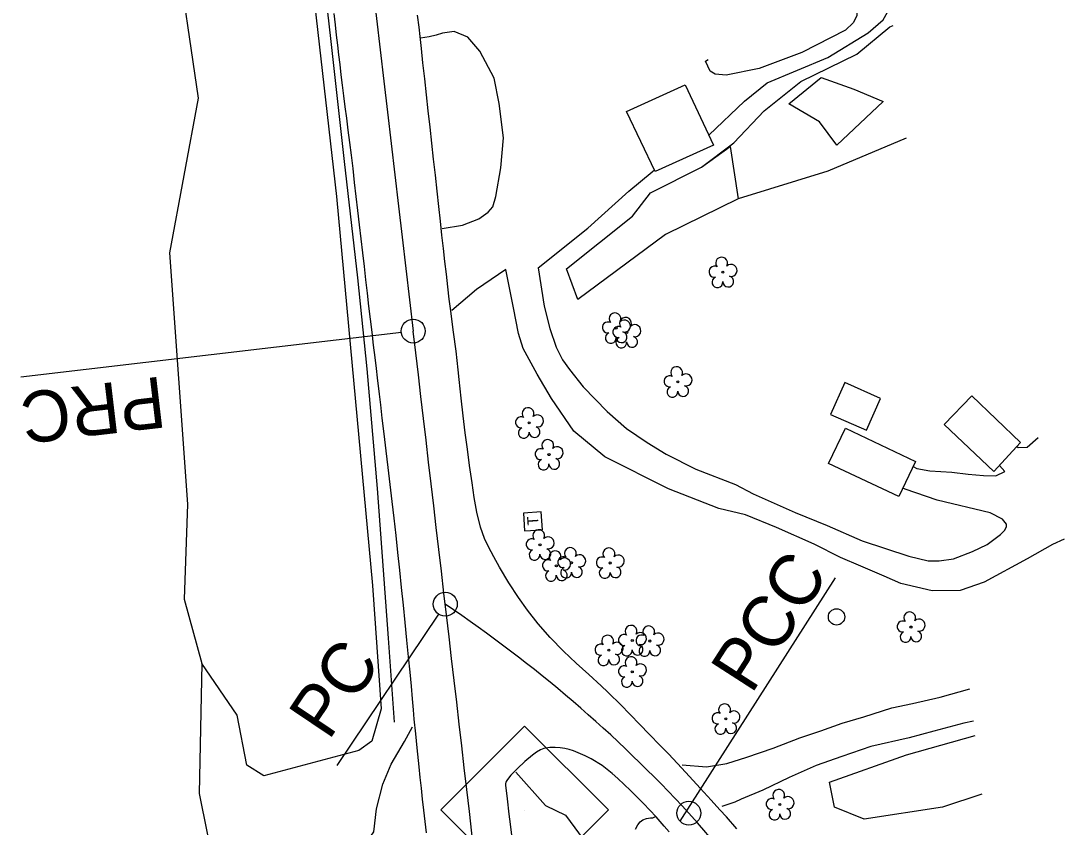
# Model space of a CAD drawing. Extents: x 476627 to 479509, y 495837 to 499842.
# Drawn here: x 477971.3 to 478298.1, y 497616.9 to 497869.6 of the extents above; entities that cross this region are included whole.
import ezdxf

# ---------------------------------------------------------------- set-up
doc = ezdxf.new("R2010")
doc.units = 0
for name, color, linetype in [('CTL Secondary Horizontal and Vertical CELL', 7, 'Continuous'), ('Exist Building Metal Canopy', 7, 'Continuous'), ('Exist Guardrail', 7, 'Continuous'), ('Exist Horizontal Alignment', 7, 'Continuous'), ('Exist Other Culture Well CELL', 7, 'Continuous'), ('Exist Roads EOP', 7, 'Continuous'), ('Exist Roads EOP Other', 7, 'Continuous'), ('Exist Roads Soil', 7, 'Continuous'), ('Exist Utilities Telephone Pedestal CELL', 7, 'Continuous'), ('Exist Vegetation Hedge Row', 7, 'Continuous'), ('Exist Vegetation Tree CELL', 7, 'Continuous'), ('Exist Vegetation Woods Line', 7, 'Continuous')]:
    doc.layers.add(name, color=color, linetype=linetype)

msp = doc.modelspace()

# ---------------------------------------------------------------- linework, layer by layer
at = {"layer": 'CTL Secondary Horizontal and Vertical CELL'}
msp.add_line((478128.95, 497622.27), (478128.95, 497622.27), dxfattribs=at)
msp.add_lwpolyline([(478102.87, 497622.36), (478129.08, 497648.57), (478155.33, 497622.32), (478129.13, 497596.11)], close=True, dxfattribs=at)
at = {"layer": 'Exist Building Metal Canopy'}
for points in [[(478179.35, 497849.53), (478188.26, 497830.61), (478169.99, 497822.42), (478160.98, 497841.23)], [(478224.89, 497746.19), (478236.2, 497741.3), (478240.55, 497751.23), (478229.44, 497756.28)]]:
    msp.add_lwpolyline(points, close=True, dxfattribs=at)
for points in [[(478269.23, 497752.05), (478284.47, 497737.42), (478276.12, 497728.32), (478260.55, 497743.12), (478269.23, 497752.05)], [(478229.68, 497741.92), (478251.56, 497731.45), (478246.35, 497720.51), (478224.32, 497730.87), (478229.68, 497741.92)]]:
    msp.add_lwpolyline(points, dxfattribs=at)
at = {"layer": 'Exist Guardrail'}
msp.add_line((478088.31, 497649.84), (478086.46, 497676.11), dxfattribs=at)
msp.add_lwpolyline([(478086.46, 497676.11), (478082.96, 497723.06), (478079.76, 497760.55), (478076.82, 497789.03), (478072.71, 497825.54), (478068.52, 497863.08), (478065.12, 497892.72), (478060.78, 497929.66), (478056.27, 497968.59), (478052.93, 497997.1), (478051.65, 498003.96), (478049.7, 498012.85), (478047.39, 498020.65), (478045.09, 498026.62), (478042.93, 498030.39), (478040.52, 498033.29), (478038.53, 498035.24)], dxfattribs=at)
at = {"layer": 'Exist Horizontal Alignment'}
for p, q in [((478090.48, 497771.93), (477971.28, 497757.89)), ((478177.81, 497618.75), (478226.54, 497695.05)), ((478102.15, 497683.65), (478070.24, 497636.24))]:
    msp.add_line(p, q, dxfattribs=at)
for centre in [(478094.21, 497772.37), (478104.25, 497686.76), (478180.56, 497621.29)]:
    msp.add_circle(centre, 3.75, dxfattribs=at)
for centre, radius, start, end in [((592937.27, 511299.31), 115636.96, 186.405023, 186.7177067), ((394030.15, 487870.77), 84645.18, 6.5684633, 6.7177067), ((477862.62, 497327.87), 432.64, 42.703, 56.0491), ((478049.09, 497499.96), 178.91, 1.7193, 42.703)]:
    msp.add_arc(centre, radius, start, end, dxfattribs=at)
at = {"layer": 'Exist Other Culture Well CELL'}
msp.add_circle((478226.82, 497682.8), 2.56, dxfattribs=at)
at = {"layer": 'Exist Roads EOP'}
for points in [[(478098.33, 497615.17), (478097.92, 497618.72), (478097.53, 497622.22), (478097.15, 497625.68), (478096.78, 497629.11), (478096.42, 497632.5), (478096.07, 497635.85), (478095.45, 497641.77), (478094.99, 497646.15), (478094.54, 497650.71), (478094.27, 497653.7), (478093.96, 497657.16), (478093.61, 497661.08), (478093.2, 497665.45), (478092.74, 497670.26), (478092.22, 497675.53), (478091.68, 497681.01), (478091.12, 497686.5), (478090.56, 497691.99), (478089.98, 497697.47), (478089.4, 497702.93), (478088.81, 497708.34), (478088.2, 497713.7), (478087.58, 497719), (478086.96, 497724.28), (478086.34, 497729.57), (478085.71, 497734.86), (478085.09, 497740.16), (478084.52, 497745.08), (478084.03, 497749.23), (478083.64, 497752.62), (478083.04, 497757.71), (478082.69, 497760.64), (478082.27, 497764.04), (478081.79, 497767.9), (478081.29, 497771.99), (478080.79, 497776.08), (478080.31, 497780.17), (478079.84, 497784.25), (478079.37, 497788.38), (478078.89, 497792.59), (478078.39, 497796.89), (478077.88, 497801.27), (478077.37, 497805.69), (478076.86, 497810.11), (478076.35, 497814.54), (478075.85, 497818.97), (478075.34, 497823.32), (478074.84, 497827.49), (478074.35, 497831.5), (478073.85, 497835.35), (478073.37, 497839.05), (478072.91, 497842.63), (478072.47, 497846.1), (478072.06, 497849.45), (478071.66, 497852.7), (478071.28, 497855.89), (478070.92, 497858.99), (478070.56, 497862.02), (478070.2, 497865.11), (478069.81, 497868.39), (478069.39, 497871.86)], [(478195.57, 497616.38), (478192.3, 497620.11), (478190.28, 497622.34), (478187.54, 497625.34), (478184.08, 497629.11), (478180.71, 497632.78), (478178.25, 497635.45), (478174.28, 497639.72), (478171.93, 497642.14), (478167.82, 497646.35), (478165.49, 497648.73), (478161.85, 497652.48), (478159.42, 497655.02), (478155.17, 497659.23), (478153.05, 497661.22), (478149.2, 497664.75), (478145.27, 497668.34), (478141.28, 497672.07), (478137.15, 497676.29), (478133.39, 497680.57), (478129.98, 497684.91), (478127.17, 497688.84), (478124.14, 497693.42), (478121.2, 497698.37), (478119.41, 497701.57), (478117.74, 497704.75), (478116.53, 497707.35), (478115.25, 497710.94), (478114.16, 497715.58), (478113.34, 497720.26), (478112.65, 497724.81), (478111.87, 497730.19), (478111.17, 497735.37), (478110.52, 497740.51), (478109.88, 497745.8), (478109.25, 497751.32), (478108.64, 497757.2), (478108.32, 497760.21), (478107.61, 497766.12), (478106.81, 497772), (478106.39, 497775.23), (478105.96, 497778.7), (478105.51, 497782.4), (478105.06, 497786.26), (478104.61, 497790.18), (478104.14, 497794.16), (478103.68, 497798.22), (478103.2, 497802.41), (478102.71, 497806.81), (478102.2, 497811.42), (478101.68, 497816.25), (478101.14, 497821.2), (478100.59, 497826.2), (478100.03, 497831.24), (478099.46, 497836.32), (478098.89, 497841.4), (478098.33, 497846.45), (478097.79, 497851.44), (478097.26, 497856.4), (478096.78, 497860.93), (478096.37, 497864.67), (478096.04, 497867.6), (478095.58, 497871.4)], [(478174.34, 497615.4), (478172.82, 497617.23), (478170.28, 497620.15), (478166.39, 497624.26), (478162.27, 497628.37), (478158.27, 497632.18), (478156.51, 497633.76), (478153.4, 497636.25), (478149.97, 497638.31), (478148.07, 497639.28), (478144.46, 497640.85), (478143.09, 497641.27), (478141.69, 497641.58), (478140.22, 497641.8), (478138.64, 497641.88), (478137.02, 497641.82), (478135.68, 497641.65), (478135.14, 497641.52), (478134.62, 497641.35), (478134.07, 497641.1), (478132.85, 497640.4), (478131.6, 497639.5), (478129.2, 497637.44), (478126.84, 497635.25), (478124.8, 497633.19), (478123.74, 497631.83), (478123.35, 497631.25), (478123.25, 497631.04), (478123.18, 497630.82), (478123.15, 497630.59), (478123.16, 497630.1), (478123.62, 497625.82), (478124.18, 497620.94), (478124.55, 497617.86), (478124.99, 497614.35)]]:
    msp.add_lwpolyline(points, dxfattribs=at)
at = {"layer": 'Exist Roads EOP Other'}
for points in [[(478040.39, 497497.33), (478038, 497503.84), (478031.05, 497502.21), (478029.65, 497506.59), (478030.19, 497509.74), (478032.84, 497514.28), (478037.55, 497522.57), (478043.79, 497537.51), (478049.23, 497546.44), (478051.66, 497555.02), (478056.01, 497569.24), (478059.93, 497580.91), (478065.41, 497592.04), (478069.76, 497599.5), (478075.6, 497606.48), (478081.89, 497615.39), (478082.65, 497622.65), (478084.7, 497630.36), (478087.33, 497636.61), (478091.49, 497643.73), (478093.96, 497648.37)], [(478126.3, 497634.08), (478135.61, 497623.71), (478141.86, 497620.68), (478148.86, 497611.15)], [(478163.88, 497616.28), (478164.6, 497617.61), (478165.33, 497618.53), (478166.13, 497619.15), (478167.29, 497619.56), (478168.52, 497619.83), (478169.29, 497619.8), (478170.27, 497620.29)]]:
    msp.add_lwpolyline(points, dxfattribs=at)
at = {"layer": 'Exist Roads Soil'}
for points in [[(478186.79, 497833.73), (478198.04, 497844.42), (478205.11, 497850.12), (478224.08, 497858.1), (478236.7, 497865.83), (478241.46, 497869.88), (478242.83, 497872.32), (478242.26, 497877.8), (478240.27, 497880.71), (478237.86, 497884.4), (478231.22, 497880.88), (478232.53, 497876.89), (478233.19, 497874), (478233.15, 497871.19), (478232.08, 497869.02), (478229.65, 497866.7), (478215.95, 497859.69), (478202.54, 497854.7), (478192.27, 497852.52), (478188.79, 497852.84), (478187.2, 497853.84), (478185.72, 497856.99), (478186.63, 497857.46)], [(478103.28, 497804.51), (478109.62, 497805.55), (478114.77, 497807.54), (478117.71, 497809.59), (478119.18, 497811.35), (478120.11, 497814.56), (478121.61, 497823.48), (478122.5, 497832.9), (478121.1, 497843.66), (478119.53, 497851.59), (478115.07, 497860.11), (478111.3, 497864.53), (478107.05, 497866.24), (478103.33, 497865.76), (478101.36, 497865.15), (478099.22, 497864.58), (478096.47, 497864.19)], [(478133.3, 497792.18), (478148.89, 497804.59), (478161.79, 497816.19), (478169.05, 497822.29), (478169.77, 497822.87)], [(478123.2, 497791.66), (478114.01, 497785.44), (478106.26, 497778.83)], [(478219.78, 497705.57), (478208.03, 497710.77), (478198.3, 497714.8), (478189.94, 497716.75), (478174.2, 497722.9), (478154.2, 497732.95), (478144.55, 497741.02), (478137.52, 497751.19), (478133, 497758.89), (478128.69, 497766.92), (478127.17, 497771.61), (478125.62, 497779.66), (478123.2, 497791.66)], [(478133.3, 497792.18), (478135.19, 497780.22), (478137.01, 497773.16), (478139.03, 497767.33), (478140.99, 497763.39), (478143.2, 497760.28), (478147.47, 497754.92), (478155.01, 497747.15), (478161.05, 497741.86), (478167.47, 497737.4), (478173.47, 497733.74), (478182.78, 497729.08), (478195.16, 497724.28), (478200.67, 497721.31), (478213.82, 497715.5), (478223.87, 497711.43)], [(478283.36, 497736.21), (478283.68, 497735.88), (478286.59, 497735.94), (478289.99, 497739.04)], [(478250.82, 497729.9), (478252.03, 497729.34), (478256.07, 497728.56), (478262.98, 497728.19), (478268.11, 497727.57), (478272.9, 497727.08), (478276.73, 497727.02), (478279.58, 497728.41), (478277.89, 497730.25)], [(478223.87, 497711.43), (478234.9, 497706.6), (478249.46, 497701.86), (478255.56, 497700.36), (478259.03, 497700.35), (478263.46, 497700.99), (478269.41, 497703.3), (478274.06, 497705.52), (478278.19, 497708.6), (478279.51, 497709.98), (478280.11, 497711.08), (478280.1, 497711.88), (478278.79, 497713.45), (478274.94, 497715.36), (478258.31, 497719.41), (478248.37, 497722.82)], [(478248.37, 497722.82), (478247.61, 497723.16)], [(478298.13, 497707.13), (478294.52, 497705.53), (478286.6, 497700.94), (478273.03, 497693.71), (478265.57, 497691.07), (478256.75, 497690.97), (478247, 497693.29), (478241.7, 497695.57), (478234.4, 497698.7), (478228.04, 497701.4), (478219.78, 497705.57)], [(478178.46, 497636.46), (478186.07, 497635.81), (478192.46, 497636.88), (478198.7, 497638.81), (478206.97, 497641.62), (478215.31, 497644.88), (478221.92, 497647.13), (478228.64, 497649.48), (478235.39, 497651.48), (478244.18, 497654.32), (478250.67, 497655.65), (478259.29, 497657.61), (478268.55, 497660.27)], [(478269.71, 497650.15), (478266.71, 497649.49), (478257.27, 497647.03), (478249.63, 497644.85), (478237.54, 497642.17), (478228.48, 497639.07), (478220.42, 497636.23), (478211.99, 497632.49), (478203.69, 497628.51), (478196.97, 497625.63), (478194.94, 497624.74), (478190.9, 497623.34)]]:
    msp.add_lwpolyline(points, dxfattribs=at)
at = {"layer": 'Exist Utilities Telephone Pedestal CELL'}
msp.add_line((478131.67, 497712.64), (478131.67, 497712.64), dxfattribs=at)
msp.add_lwpolyline([(478134.67, 497710.12), (478134.29, 497715.7), (478128.71, 497715.32), (478129.09, 497709.74), (478134.67, 497710.12)], dxfattribs=at)
at = {"layer": 'Exist Vegetation Hedge Row'}
for points in [[(478005.17, 497992.72), (478010.05, 498016.72), (478015.24, 498028.27), (478022.07, 498040.55), (478029.76, 498050.13), (478033.34, 498045.53), (478037.13, 498033.15), (478047.9, 498007.71), (478058.84, 497913.8), (478070.21, 497814.5), (478081.44, 497692.59)], [(478184.47, 497823.7), (478194.65, 497831.33), (478204.14, 497841.44), (478215.67, 497850.58), (478233.22, 497859.17), (478243.56, 497867.67), (478244.58, 497868.13)], [(478248.65, 497832.86), (478224.14, 497822.44), (478196, 497813.81)], [(478081.44, 497692.59), (478084.2, 497653.98), (478081.27, 497643.82), (478077.15, 497640.9), (478047.44, 497633.01), (478042.09, 497636.3), (478039.04, 497651.97), (478027.96, 497668.21)]]:
    msp.add_lwpolyline(points, dxfattribs=at)
at = {"layer": 'Exist Vegetation Tree CELL'}
for p, q in [((478191.2, 497790.8), (478191.2, 497790.8)), ((478157.79, 497773.34), (478157.79, 497773.34)), ((478161.09, 497771.9), (478161.09, 497771.9)), ((478177.12, 497756.48), (478177.12, 497756.48)), ((478130.55, 497743.61), (478130.55, 497743.61)), ((478136.73, 497733.65), (478136.73, 497733.65)), ((478133.92, 497705.39), (478133.92, 497705.39)), ((478143.81, 497699.77), (478143.81, 497699.77)), ((478139.05, 497698.77), (478139.05, 497698.77)), ((478155.89, 497699.69), (478155.89, 497699.69)), ((478250.14, 497679.61), (478250.14, 497679.61)), ((478162.84, 497675.4), (478162.84, 497675.4)), ((478168.34, 497675.23), (478168.34, 497675.23)), ((478155.48, 497672.35), (478155.48, 497672.35)), ((478162.83, 497665.58), (478162.83, 497665.58)), ((478192.13, 497650.83), (478192.13, 497650.83)), ((478209.08, 497623.98), (478209.08, 497623.98))]:
    msp.add_line(p, q, dxfattribs=at)
for centre in [(478191.2, 497790.8), (478157.79, 497773.34), (478161.09, 497771.9), (478177.12, 497756.48), (478130.55, 497743.61), (478136.73, 497733.65), (478133.92, 497705.39), (478143.81, 497699.77), (478155.89, 497699.69), (478139.05, 497698.77), (478250.14, 497679.61), (478162.84, 497675.4), (478168.34, 497675.23), (478155.48, 497672.35), (478162.83, 497665.58), (478192.13, 497650.83), (478209.08, 497623.98)]:
    msp.add_circle(centre, 0.326, dxfattribs=at)
for centre, radius, start, end in [((478190.82, 497793.68), 1.86, 330.1651, 219.7134), ((478188.6, 497790.96), 1.73, 62.6636, 279.3457), ((478193.75, 497791.39), 1.9, 257.1011, 134.1999), ((478189.5, 497787.68), 1.69, 111.5671, 6.231), ((478192.88, 497787.9), 1.7, 181.2822, 74.56), ((478155.19, 497773.5), 1.73, 62.6636, 279.3457), ((478157.41, 497776.22), 1.86, 330.1651, 219.7134), ((478160.7, 497774.78), 1.86, 330.1651, 219.7134), ((478160.34, 497773.93), 1.9, 257.1011, 134.1999), ((478156.09, 497770.22), 1.69, 111.5671, 6.231), ((478158.48, 497772.06), 1.73, 62.6636, 279.3457), ((478159.46, 497770.44), 1.7, 181.2822, 74.56), ((478163.63, 497772.49), 1.9, 257.1011, 134.1999), ((478159.38, 497768.78), 1.69, 111.5671, 6.231), ((478162.76, 497769), 1.7, 181.2822, 74.56), ((478176.73, 497759.35), 1.86, 330.1651, 219.7134), ((478179.67, 497757.07), 1.9, 257.1011, 134.1999), ((478174.51, 497756.63), 1.73, 62.6636, 279.3457), ((478175.41, 497753.36), 1.69, 111.5671, 6.231), ((478178.79, 497753.58), 1.7, 181.2822, 74.56), ((478130.17, 497746.48), 1.86, 330.1651, 219.7134), ((478133.1, 497744.2), 1.9, 257.1011, 134.1999), ((478127.95, 497743.76), 1.73, 62.6636, 279.3457), ((478132.23, 497740.71), 1.7, 181.2822, 74.56), ((478128.85, 497740.49), 1.69, 111.5671, 6.231), ((478136.34, 497736.52), 1.86, 330.1651, 219.7134), ((478139.28, 497734.24), 1.9, 257.1011, 134.1999), ((478134.12, 497733.8), 1.73, 62.6636, 279.3457), ((478135.02, 497730.53), 1.69, 111.5671, 6.231), ((478138.4, 497730.75), 1.7, 181.2822, 74.56), ((478133.54, 497708.27), 1.86, 330.1651, 219.7134), ((478131.32, 497705.55), 1.73, 62.6636, 279.3457), ((478136.47, 497705.98), 1.9, 257.1011, 134.1999), ((478132.22, 497702.27), 1.69, 111.5671, 6.231), ((478135.59, 497702.49), 1.7, 181.2822, 74.56), ((478138.66, 497701.64), 1.86, 330.1651, 219.7134), ((478143.43, 497702.65), 1.86, 330.1651, 219.7134), ((478155.51, 497702.56), 1.86, 330.1651, 219.7134), ((478136.44, 497698.92), 1.73, 62.6636, 279.3457), ((478141.21, 497699.93), 1.73, 62.6636, 279.3457), ((478141.6, 497699.36), 1.9, 257.1011, 134.1999), ((478146.36, 497700.36), 1.9, 257.1011, 134.1999), ((478153.29, 497699.84), 1.73, 62.6636, 279.3457), ((478158.44, 497700.28), 1.9, 257.1011, 134.1999), ((478137.35, 497695.65), 1.69, 111.5671, 6.231), ((478140.72, 497695.87), 1.7, 181.2822, 74.56), ((478142.11, 497696.65), 1.69, 111.5671, 6.231), ((478145.49, 497696.87), 1.7, 181.2822, 74.56), ((478154.19, 497696.57), 1.69, 111.5671, 6.231), ((478157.57, 497696.79), 1.7, 181.2822, 74.56), ((478249.76, 497682.49), 1.86, 330.1651, 219.7134), ((478247.54, 497679.77), 1.73, 62.6636, 279.3457), ((478252.69, 497680.2), 1.9, 257.1011, 134.1999), ((478155.1, 497675.22), 1.86, 330.1651, 219.7134), ((478160.24, 497675.55), 1.73, 62.6636, 279.3457), ((478162.46, 497678.27), 1.86, 330.1651, 219.7134), ((478165.74, 497675.38), 1.73, 62.6636, 279.3457), ((478165.39, 497675.99), 1.9, 257.1011, 134.1999), ((478167.96, 497678.1), 1.86, 330.1651, 219.7134), ((478170.89, 497675.82), 1.9, 257.1011, 134.1999), ((478248.44, 497676.49), 1.69, 111.5671, 6.231), ((478251.81, 497676.71), 1.7, 181.2822, 74.56), ((478152.88, 497672.5), 1.73, 62.6636, 279.3457), ((478158.03, 497672.94), 1.9, 257.1011, 134.1999), ((478161.14, 497672.28), 1.69, 111.5671, 6.231), ((478164.51, 497672.5), 1.7, 181.2822, 74.56), ((478166.64, 497672.11), 1.69, 111.5671, 6.231), ((478170.02, 497672.33), 1.7, 181.2822, 74.56), ((478153.78, 497669.23), 1.69, 111.5671, 6.231), ((478157.15, 497669.45), 1.7, 181.2822, 74.56), ((478160.23, 497665.73), 1.73, 62.6636, 279.3457), ((478162.45, 497668.45), 1.86, 330.1651, 219.7134), ((478165.38, 497666.17), 1.9, 257.1011, 134.1999), ((478161.13, 497662.46), 1.69, 111.5671, 6.231), ((478164.51, 497662.68), 1.7, 181.2822, 74.56), ((478191.75, 497653.7), 1.86, 330.1651, 219.7134), ((478189.53, 497650.98), 1.73, 62.6636, 279.3457), ((478194.68, 497651.41), 1.9, 257.1011, 134.1999), ((478190.43, 497647.7), 1.69, 111.5671, 6.231), ((478193.8, 497647.93), 1.7, 181.2822, 74.56), ((478208.7, 497626.86), 1.86, 330.1651, 219.7134), ((478206.48, 497624.14), 1.73, 62.6636, 279.3457), ((478211.63, 497624.57), 1.9, 257.1011, 134.1999), ((478207.38, 497620.86), 1.69, 111.5671, 6.231), ((478210.76, 497621.08), 1.7, 181.2822, 74.56)]:
    msp.add_arc(centre, radius, start, end, dxfattribs=at)
at = {"layer": 'Exist Vegetation Woods Line'}
for points in [[(477979.45, 498191.25), (477993.64, 498099.1), (478005.17, 497992.72), (478026.78, 497845.41), (478017.87, 497796.88), (478023.44, 497718.17), (478022.43, 497688.31), (478027.96, 497668.21)], [(478241.43, 497844.3), (478226.97, 497830.64), (478221.45, 497837.93), (478211.85, 497843.57), (478222.01, 497851.79), (478232.22, 497848.22), (478241.43, 497844.3)], [(478196, 497813.81), (478173.27, 497802.59), (478145.76, 497782.22), (478142.23, 497791.89), (478162.9, 497808.42), (478168.52, 497815.67), (478184.47, 497823.7), (478193.46, 497830.21), (478196, 497813.81)], [(478027.96, 497668.21), (478027.09, 497627.45), (478039.5, 497566.35), (478002.92, 497535.46), (477991.01, 497505.83), (477990.37, 497476.29), (477977.65, 497438.65), (477971.98, 497438.61)], [(478224.6, 497631.04), (478248.7, 497639.56), (478270.23, 497645.66)], [(478272.36, 497627.19), (478260.06, 497623.14), (478235.5, 497619.45), (478226.2, 497623.13), (478224.6, 497631.04)]]:
    msp.add_lwpolyline(points, dxfattribs=at)

# ---------------------------------------------------------------- texts
at = {"layer": 'Exist Horizontal Alignment'}
for s, rotation, p in [('PRC', 186.7177, (478015.43, 497758.18)), ('PCC', 57.2174, (478200.14, 497658.26)), ('PC', 56.0491, (478067.69, 497643.73))]:
    msp.add_text(s, height=16, rotation=rotation, dxfattribs=at).set_placement(p)
at = {"layer": 'Exist Utilities Telephone Pedestal CELL'}
msp.add_text('T', height=3.42, rotation=93.8976, dxfattribs=at).set_placement((478133.45, 497711.63))

doc.saveas('drawing.dxf')
